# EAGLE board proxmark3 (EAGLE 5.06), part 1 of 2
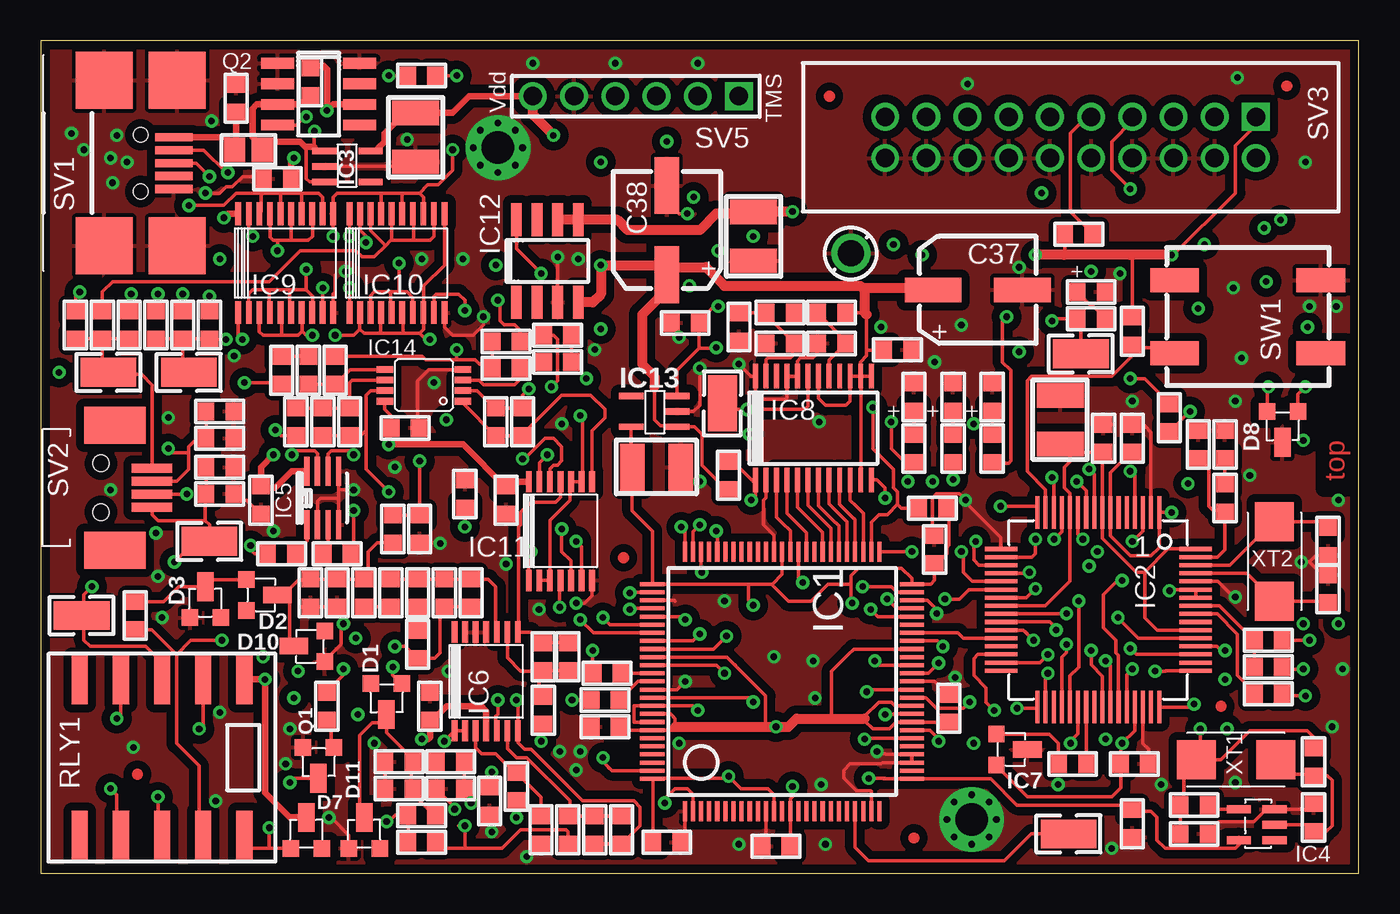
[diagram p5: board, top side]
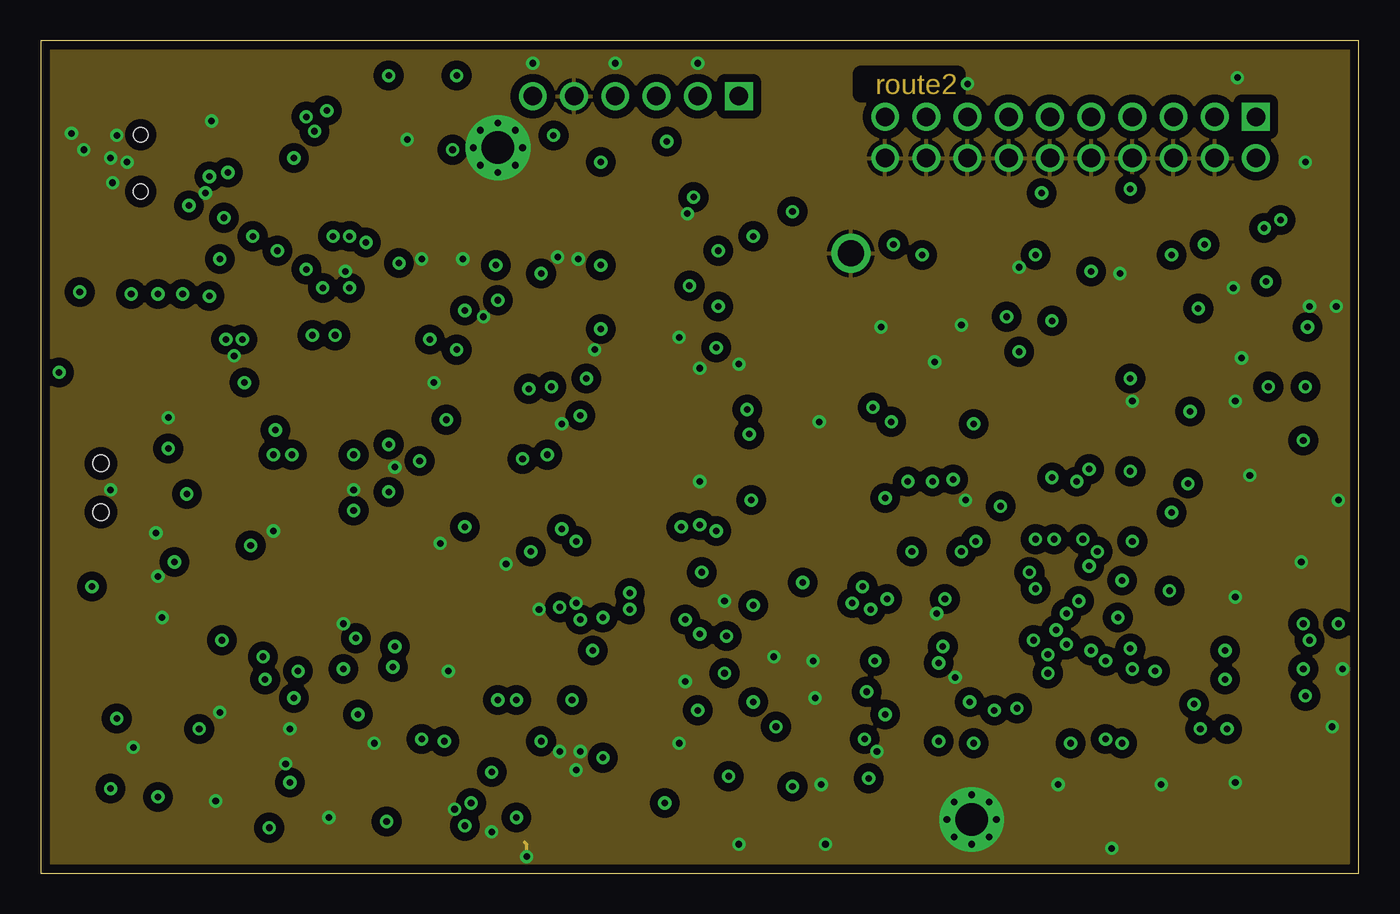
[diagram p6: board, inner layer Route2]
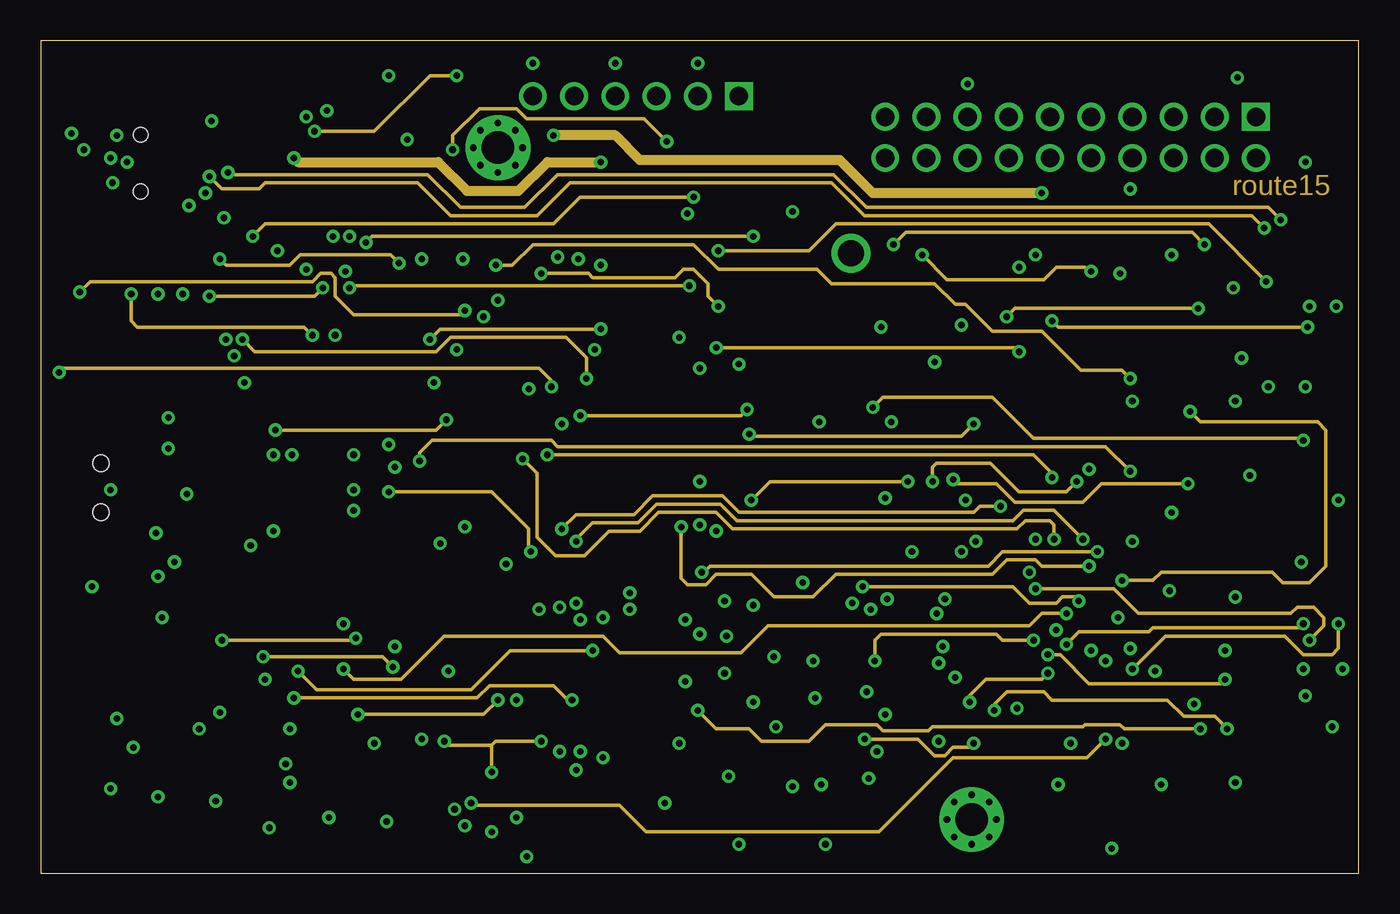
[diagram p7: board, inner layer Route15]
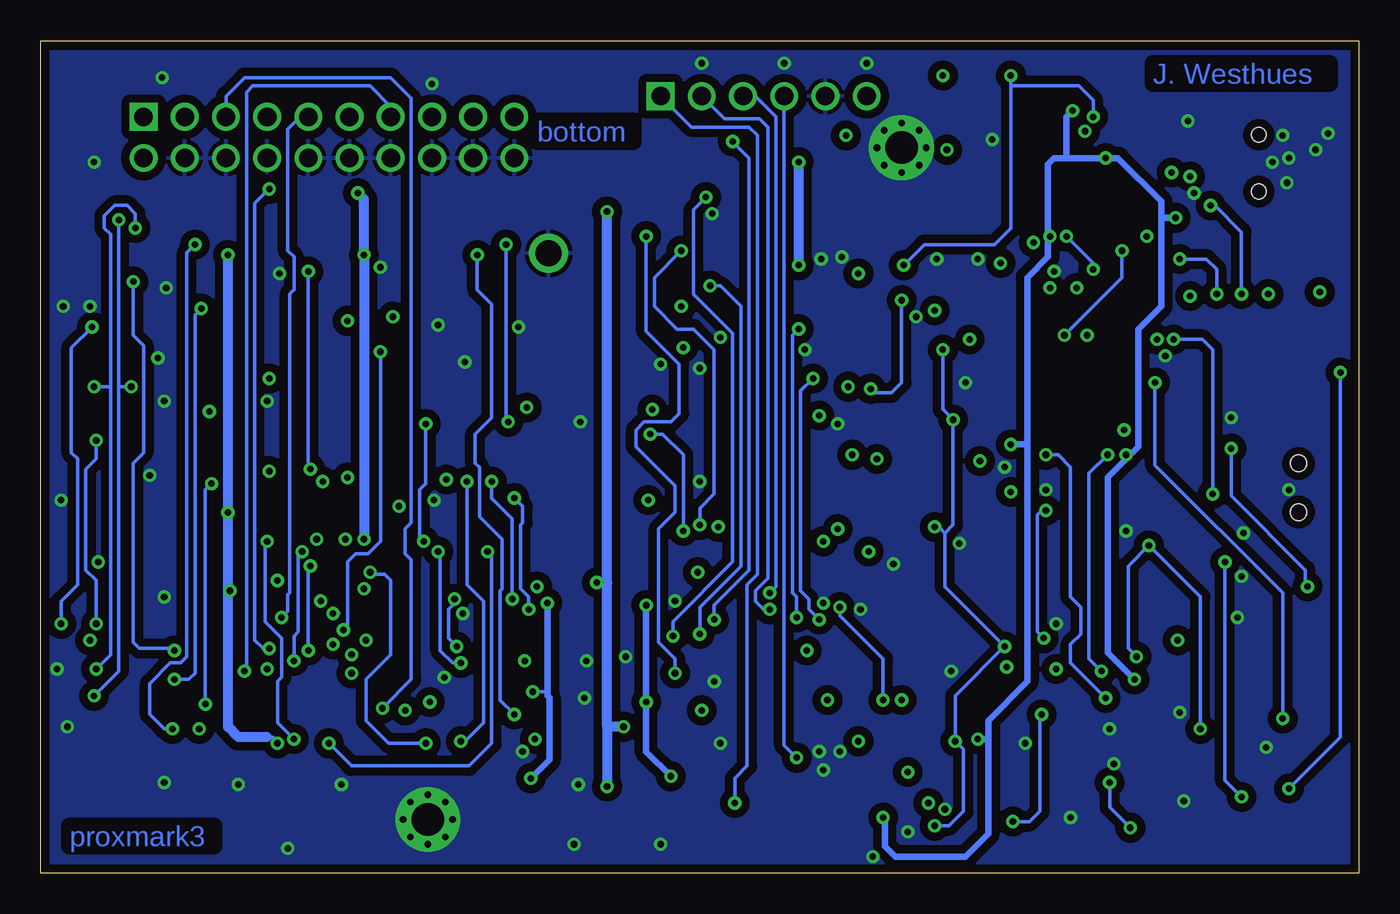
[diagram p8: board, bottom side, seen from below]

Size 81.28 x 51.31 mm. Coordinates in mm from the lower left corner, seen from the top.
Outline: 81.28,0 81.28,51.31 0,51.31 0,0 81.28,0
Copper layers (1*2*15*16): Top 0.0254mm / dielectric 0.508mm / Route2 0.0254mm / dielectric 0.508mm / Route15 0.0254mm / dielectric 0.508mm / Bottom 0.0254mm
Design rules "default *": minimum track width 8mil, minimum drill 16mil, track to track 8mil, track to pad 8mil, pad to pad 8mil, via to via 8mil, smd to smd 0mil, copper to edge 10mil, drill to drill 8mil, minimum pad ring 10mil, minimum via ring 8mil, stop-mask expansion 2mil, vias tented up to drill 16mil, thermal gap 10mil

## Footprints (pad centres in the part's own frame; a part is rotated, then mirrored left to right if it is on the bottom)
RLC_0603 = smd 1 x 1.1: 1 -0.85,0; 2 0.85,0
RLC_1210 = smd 1.5 x 2.9: 1 -1.5,0; 2 1.5,0
CAPCAITOR-ELECTROLYTIC-ALCHIP-MZA-F80 = smd 3.5 x 1.5: + 2.75,0; - -2.75,0
SOT23-3LEAD = smd 1.016 x 1.016: 1 -0.94,-0.762; 2 0.965,-0.762 | smd 1.016 x 1.778: 3 0.013,1.143
LED_0603 = smd 1 x 1.1: + -0.85,0; - 0.85,0
VQFP-100 = smd 1.25 x 0.25: 1 -8,6; 2 -8,5.5; 3 -8,5; 4 -8,4.5; 5 -8,4; 6 -8,3.5; 7 -8,3; 8 -8,2.5; 9 -8,2; 10 -8,1.5; 11 -8,1; 12 -8,0.5; 13 -8,0; 14 -8,-0.5; 15 -8,-1; 16 -8,-1.5; 17 -8,-2; 18 -8,-2.5; 19 -8,-3; 20 -8,-3.5; 21 -8,-4; 22 -8,-4.5; 23 -8,-5; 24 -8,-5.5; 25 -8,-6; 51 8,-6; 52 8,-5.5; 53 8,-5; 54 8,-4.5; 55 8,-4; 56 8,-3.5; 57 8,-3; 58 8,-2.5; 59 8,-2; 60 8,-1.5; 61 8,-1; 62 8,-0.5; 63 8,0; 64 8,0.5; 65 8,1; 66 8,1.5; 67 8,2; 68 8,2.5; 69 8,3; 70 8,3.5; 71 8,4; 72 8,4.5; 73 8,5; 74 8,5.5; 75 8,6 | smd 0.25 x 1.5: 26 -6,-8; 27 -5.5,-8; 28 -5,-8; 29 -4.5,-8; 30 -4,-8; 31 -3.5,-8; 32 -3,-8; 33 -2.5,-8; 34 -2,-8; 35 -1.5,-8; 36 -1,-8; 37 -0.5,-8; 38 0,-8; 39 0.5,-8; 40 1,-8; 41 1.5,-8; 42 2,-8; 43 2.5,-8; 44 3,-8; 45 3.5,-8; 46 4,-8; 47 4.5,-8; 48 5,-8; 49 5.5,-8; 50 6,-8; 76 6,8; 77 5.5,8; 78 5,8; 79 4.5,8; 80 4,8; 81 3.5,8; 82 3,8; 83 2.5,8; 84 2,8; 85 1.5,8; 86 1,8; 87 0.5,8; 88 0,8; 89 -0.5,8; 90 -1,8; 91 -1.5,8; 92 -2,8; 93 -2.5,8; 94 -3,8; 95 -3.5,8; 96 -4,8; 97 -4.5,8; 98 -5,8; 99 -5.5,8; 100 -6,8
LQFP-64 = smd 0.25 x 2: 1 0,0; 2 0.5,0; 3 1,0; 4 1.5,0; 5 2,0; 6 2.5,0; 7 3,0; 8 3.5,0; 9 4,0; 10 4.5,0; 11 5,0; 12 5.5,0; 13 6,0; 14 6.5,0; 15 7,0; 16 7.5,0; 33 7.5,12; 34 7,12; 35 6.5,12; 36 6,12; 37 5.5,12; 38 5,12; 39 4.5,12; 40 4,12; 41 3.5,12; 42 3,12; 43 2.5,12; 44 2,12; 45 1.5,12; 46 1,12; 47 0.5,12; 48 0,12 | smd 2 x 0.25: 17 9.75,2.25; 18 9.75,2.75; 19 9.75,3.25; 20 9.75,3.75; 21 9.75,4.25; 22 9.75,4.75; 23 9.75,5.25; 24 9.75,5.75; 25 9.75,6.25; 26 9.75,6.75; 27 9.75,7.25; 28 9.75,7.75; 29 9.75,8.25; 30 9.75,8.75; 31 9.75,9.25; 32 9.75,9.75; 49 -2.25,9.75; 50 -2.25,9.25; 51 -2.25,8.75; 52 -2.25,8.25; 53 -2.25,7.75; 54 -2.25,7.25; 55 -2.25,6.75; 56 -2.25,6.25; 57 -2.25,5.75; 58 -2.25,5.25; 59 -2.25,4.75; 60 -2.25,4.25; 61 -2.25,3.75; 62 -2.25,3.25; 63 -2.25,2.75; 64 -2.25,2.25
SOT-23-5 = smd 0.4 x 1.5: 1 -0.94,-1.422; 2 0.01,-1.422; 3 0.96,-1.422; 4 0.96,1.428; 5 -0.94,1.428
SMV-5 = smd 1.5 x 0.5: 1 0,0; 2 0,-0.95; 3 0,-1.9; 4 2.2,-1.9; 5 2.2,0
SOT-23-8-OR-MSOP-8 = smd 0.325 x 1.8: 1 -0.975,-1.65; 2 -0.325,-1.65; 3 0.325,-1.65; 4 0.975,-1.65; 5 0.975,1.65; 6 0.325,1.65; 7 -0.325,1.65; 8 -0.975,1.65
TSSOP-14 = smd 1.3 x 0.36: 1 0,0; 2 0,-0.65; 3 0,-1.3; 4 0,-1.95; 5 0,-2.6; 6 0,-3.25; 7 0,-3.9; 8 6.095,-3.9; 9 6.095,-3.25; 10 6.095,-2.6; 11 6.095,-1.95; 12 6.095,-1.3; 13 6.095,-0.65; 14 6.095,0
TSSOP-24 = smd 0.3 x 1.5: 1 -2.925,-3.2; 2 -2.275,-3.2; 3 -1.625,-3.2; 4 -0.975,-3.2; 5 -0.325,-3.2; 6 0.325,-3.2; 7 0.975,-3.2; 8 1.625,-3.2; 9 2.275,-3.2; 10 2.925,-3.2; 11 3.575,-3.2; 12 4.225,-3.2; 13 4.225,3.2; 14 3.575,3.2; 15 2.925,3.2; 16 2.275,3.2; 17 1.625,3.2; 18 0.975,3.2; 19 0.325,3.2; 20 -0.325,3.2; 21 -0.975,3.2; 22 -1.625,3.2; 23 -2.275,3.2; 24 -2.925,3.2
TSSOP-20 = smd 1.4 x 0.36: 1 0,0; 2 0,-0.65; 3 0,-1.3; 4 0,-1.95; 5 0,-2.6; 6 0,-3.25; 7 0,-3.9; 8 0,-4.55; 9 0,-5.2; 10 0,-5.85; 11 6.095,-5.85; 12 6.095,-5.2; 13 6.095,-4.55; 14 6.095,-3.9; 15 6.095,-3.25; 16 6.095,-2.6; 17 6.095,-1.95; 18 6.095,-1.3; 19 6.095,-0.65; 20 6.095,0
SOIC-8 = smd 0.66 x 2.032: 1 0,0; 2 1.27,0; 3 2.54,0; 4 3.81,0; 5 3.81,5.08; 6 2.54,5.08; 7 1.27,5.08; 8 0,5.08
MSOP8 = smd 0.41 x 1.02: 1 0,0; 2 0.65,0; 3 1.3,0; 4 1.95,0; 5 1.95,4.8; 6 1.3,4.8; 7 0.65,4.8; 8 0,4.8
TQ-SMD-RELAY = smd 1 x 3: 1 -5.08,-4.78; 2 -2.54,-4.78; 3 0,-4.78; 4 2.54,-4.78; 5 5.08,-4.78; 6 5.08,4.78; 7 2.54,4.78; 8 0,4.78; 9 -2.54,4.78; 10 -5.08,4.78
USB-MINIB-SMD = smd 2.3 x 0.5: 1 2,0.4; 2 2,-0.4; 3 2,-1.2; 4 2,-2; 5 2,-2.8 | smd 3.5 x 3.5: TAB0 -2.3,3.9; TAB1 2.2,3.9; TAB2 2.2,-6.3; TAB3 -2.3,-6.3 | hole 0.9: -0.05,0.55; -0.05,-2.95
HIROSE-MQ172-4POS = smd 0.55 x 2.5: 1 -1.2,6.75; 2 -0.4,6.75; 3 0.4,6.75; 4 1.2,6.75 | smd 2.3 x 3.8: P$1 -3.85,4.45; P$2 3.85,4.45 | hole 1: -1.5,3.6; 1.5,3.6
HEADER-MALE-10X2-0.100-SHROUDED = drill 1.143 square: 1 -1.27,11.43 | drill 1.143 round: 2 1.27,11.43; 3 -1.27,8.89; 4 1.27,8.89; 5 -1.27,6.35; 6 1.27,6.35; 7 -1.27,3.81; 8 1.27,3.81; 9 -1.27,1.27; 10 1.27,1.27; 11 -1.27,-1.27; 12 1.27,-1.27; 13 -1.27,-3.81; 14 1.27,-3.81; 15 -1.27,-6.35; 16 1.27,-6.35; 17 -1.27,-8.89; 18 1.27,-8.89; 19 -1.27,-11.43; 20 1.27,-11.43
HEADER-MALE-6X1-0.100-UNKEYED = drill 1.143 square: 1 0,6.35 | drill 1.143 round: 2 0,3.81; 3 0,1.27; 4 0,-1.27; 5 0,-3.81; 6 0,-6.35
TACTSWITCH-SMD-EVQQ1 = smd 1.5 x 3: A -2.25,4.5; B 2.25,-4.5; P$2 2.25,4.5; P$3 -2.25,-4.5
KEYSTONE-SMD-TESTPOINT-5015 = smd 3.429 x 1.778: 1 0,0
KEYSTONE-PTH-TESTPOINT-5011 = drill 1.6 round: A 0,0
RLC_0805 = smd 1.3 x 1.5: 1 -0.85,0; 2 0.85,0
XTAL-SMD-CITIZEN-CS10 = smd 2.4 x 2.4: A -0.2,0; B 4.7,0

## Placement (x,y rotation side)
C1  33n  [RLC_0603]  12.06,47.75 90 top
C2  22p  [RLC_0603]  78.49,3.43 90 top
C3  22p  [RLC_0603]  71.12,2.41 0 top
C4  33n  [RLC_0603]  73.03,26.42 270 top
C5  2n  [RLC_0603]  71.37,26.42 270 top
C6  22p  [RLC_0603]  79.38,17.53 270 top
C7  22p  [RLC_0603]  79.38,20.45 90 top
C8  1n  [RLC_0603]  65.53,26.8 90 top
C9  2u2  [RLC_1210]  62.87,27.94 90 top
C10  100n  [RLC_0603]  27.69,4.45 270 top
C11  1n  [RLC_0603]  22.1,6.86 180 top
C12  1n  [RLC_0603]  23.5,3.56 180 top
C13  dnp  [RLC_0603]  35.81,2.67 270 top
C14  22p  [RLC_0603]  5.84,15.88 90 top
C15  130p  [RLC_0603]  16.64,17.27 270 top
C16  1n  [RLC_0603]  21.59,17.27 90 top
C17  dnp  [RLC_0603]  32.51,13.34 90 top
C18  33n  [RLC_0603]  45.59,32.64 180 top
C19  33n  [RLC_0603]  48.77,32.64 180 top
C20  dnp  [RLC_0603]  11.05,28.45 0 top
C21  33n  [RLC_0603]  24,10.29 90 top
C22  33n  [RLC_0603]  22.48,27.43 0 top
C23  33n  [RLC_0603]  13.59,22.99 270 top
C24  33n  [RLC_0603]  28.7,22.99 270 top
C25  33n  [RLC_0603]  67.44,6.73 0 top
C26  33n  [RLC_0603]  67.31,26.8 90 top
C27  4u7  [RLC_1210]  23.11,45.34 270 top
C28  33n  [RLC_0603]  38.61,1.91 0 top
C29  33n  [RLC_0603]  34.8,9.02 180 top
C30  33n  [RLC_0603]  45.34,1.65 180 top
C31  33n  [RLC_0603]  56.01,10.16 90 top
C32  33n  [RLC_0603]  55.12,19.94 90 top
C33  4u7  [RLC_1210]  43.94,39.24 270 top
C34  4u7  [RLC_1210]  37.97,25.02 0 top
C35  47p  [RLC_0603]  11.05,25.02 0 top
C36  dnp  [RLC_0603]  11.05,23.37 0 top
C37  100u  [CAPCAITOR-ELECTROLYTIC-ALCHIP-MZA-F80]  57.78,35.94 180 top
C38  100u  [CAPCAITOR-ELECTROLYTIC-ALCHIP-MZA-F80]  38.61,39.62 270 top
C39  1n  [RLC_0603]  11.05,26.8 0 top
C40  dnp  [RLC_0603]  29.72,27.81 270 top
C41  dnp  [RLC_0603]  19.05,27.81 270 top
C42  1n  [RLC_0603]  31.88,33.15 0 top
C43  1n  [RLC_0603]  14.86,30.99 90 top
C44  33n  [RLC_0603]  52.83,32.26 0 top
C45  100n  [RLC_0603]  26.16,23.37 90 top
C46  33n  [RLC_0603]  14.61,42.8 180 top
C47  33n  [RLC_0603]  67.31,3.05 270 top
D1  DIODE-SMD-SOT23  [SOT23-3LEAD]  21.34,10.92 180 top
D2  DIODE-SMD-SOT23  [SOT23-3LEAD]  13.46,17.14 270 top
D3  DIODE-SMD-SOT23  [SOT23-3LEAD]  10.16,16.51 0 top
D4  LED  [LED_0603]  56.26,29.34 90 top
D5  LED  [LED_0603]  58.67,29.34 90 top
D6  LED  [LED_0603]  53.85,29.34 90 top
D7  DIODE-SMD-SOT23  [SOT23-3LEAD]  16.38,2.29 0 top
D8  DUAL-TVS-COMMON-ANODE  [SOT23-3LEAD]  76.58,27.69 180 top
D9  LED  [LED_0603]  64.77,35.81 0 top
D10  DIODE-SMD-SOT23  [SOT23-3LEAD]  16.76,13.97 90 top
D11  DIODE-SMD-SOT23  [SOT23-3LEAD]  19.94,2.29 0 top
IC1  SPARTAN-II-XC2S30-100-VQFP  [VQFP-100]  45.72,11.81 90 top
IC2  AT91SAM7S64  [LQFP-64]  68.96,22.23 180 top
IC3  PQ1X331M2ZP-3V3-LDO-SOT-23-5  [SOT-23-5]  18.92,43.56 270 top
IC4  HCU-INVERTER  [SMV-5]  76.07,2.03 180 top
IC5  TLV3502  [SOT-23-8-OR-MSOP-8]  17.4,23.11 0 top
IC6  MCP6294  [TSSOP-14]  25.53,8.76 90 top
IC7  MCP100  [SOT23-3LEAD]  59.69,7.62 270 top
IC8  TLC5540  [TSSOP-24]  46.99,27.43 0 top
IC9  74XX244-OCTAL-TRISTATE-BUFFERS  [TSSOP-20]  12.19,34.54 90 top
IC10  74XX244-OCTAL-TRISTATE-BUFFERS  [TSSOP-20]  19.05,34.54 90 top
IC11  CD4066  [TSSOP-14]  30.1,18.03 90 top
IC12  LP2989AIM-2.5  [SOIC-8]  29.34,35.18 0 top
IC13  PQ1X331M2ZP-3V3-LDO-SOT-23-5  [SOT-23-5]  37.85,28.45 90 top
IC14  AD8052  [MSOP8]  26.04,29.08 90 top
Q1  NPN-SOT23-2N3904  [SOT23-3LEAD]  17.14,6.99 180 top
Q2  IRF7307  [SOIC-8]  14.61,49.91 270 top
R1  1meg  [RLC_0603]  78.49,6.86 90 top
R2  100  [RLC_0603]  71.12,4.19 180 top
R3  330  [RLC_0603]  73.03,23.11 270 top
R4  27  [RLC_0603]  75.69,11.05 180 top
R5  27  [RLC_0603]  75.69,12.7 180 top
R6  1k5  [RLC_0603]  75.69,14.35 0 top
R7  10k  [RLC_0603]  64.01,39.37 180 top
R8  10k  [RLC_0603]  63.63,6.73 0 top
R9  100k  [RLC_0603]  29.34,5.33 270 top
R10  100k  [RLC_0603]  30.86,2.67 90 top
R11  510k  [RLC_0603]  22.1,5.21 0 top
R12  100k  [RLC_0603]  23.5,1.91 180 top
R13  10k  [RLC_0603]  32.51,2.67 90 top
R14  10k  [RLC_0603]  34.16,2.67 270 top
R15  10k  [RLC_0603]  18.29,17.27 90 top
R16  zerohm  [RLC_0603]  19.94,17.27 270 top
R17  10k  [RLC_0603]  24.89,17.27 90 top
R18  10k  [RLC_0603]  30.99,13.34 90 top
R19  10k  [RLC_0603]  30.99,10.03 90 top
R20  240k  [RLC_0603]  14.86,19.68 0 top
R21  24k  [RLC_0603]  18.29,19.68 180 top
R22  33  [RLC_0603]  5.46,33.78 270 top
R23  1k  [RLC_0603]  39.75,33.91 0 top
R24  330  [RLC_0603]  56.26,26.16 90 top
R25  330  [RLC_0603]  58.67,26.16 90 top
R26  330  [RLC_0603]  53.85,26.16 90 top
R27  33  [RLC_0603]  7.11,33.78 270 top
R28  33  [RLC_0603]  3.81,33.78 270 top
R29  33  [RLC_0603]  8.76,33.78 270 top
R30  10meg  [RLC_0603]  25.27,6.86 0 top
R31  240k  [RLC_0603]  25.27,5.21 0 top
R32  zerohm  [RLC_0603]  16.51,30.99 270 top
R33  2k4  [RLC_0603]  28.07,27.81 270 top
R34  10k  [RLC_0603]  17.4,27.81 270 top
R35  zerohm  [RLC_0603]  31.88,31.5 180 top
R36  dnp  [RLC_0603]  26.54,17.27 90 top
R37  dnp  [RLC_0603]  23.24,17.27 270 top
R38  dnp  [RLC_0603]  23.24,14.1 90 top
R39  1k  [RLC_0603]  34.92,12.32 0 top
R40  10k  [RLC_0603]  17.65,10.29 270 top
R41  10meg  [RLC_0603]  21.72,21.21 90 top
R42  1meg  [RLC_0603]  23.37,21.21 90 top
R43  1k  [RLC_0603]  67.31,33.4 90 top
R44  1k  [RLC_0603]  34.8,10.67 0 top
R45  10k  [RLC_0603]  10.41,33.78 270 top
R46  10k  [RLC_0603]  2.16,33.78 270 top
R47  10k  [RLC_0603]  42.42,24.51 90 top
R48  dnp  [RLC_0603]  18.16,30.99 270 top
R49  2k4  [RLC_0603]  28.7,31.11 0 top
R50  10k  [RLC_0603]  15.75,27.81 90 top
R51  2k4  [RLC_0603]  28.7,32.77 0 top
R52  100  [RLC_0603]  48.77,34.54 0 top
R53  330  [RLC_0603]  45.59,34.54 0 top
R54  100  [RLC_0603]  43.05,33.66 90 top
R55  330  [RLC_0603]  64.77,34.16 0 top
R56  10k  [RLC_0603]  23.5,49.15 0 top
R57  10k  [RLC_0603]  69.6,28.07 90 top
R58  dnp  [RLC_0603]  16.64,48.77 270 top
R59  3k3  [RLC_0603]  54.99,22.48 0 top
RLY1  RELAY-DPDT  [TQ-SMD-RELAY]  7.49,7.11 180 top
SV1  USB-MINIB  [USB-MINIB-SMD]  6.22,44.96 0 top
SV2  HIROSE-MQ172-4POS  [HIROSE-MQ172-4POS]  0.13,23.75 270 top
SV3  JTAG  [HEADER-MALE-10X2-0.100-SHROUDED]  63.5,45.34 270 top
SV5  HEADER-MALE-6X1  [HEADER-MALE-6X1-0.100-UNKEYED]  36.7,47.88 270 top
SW1  TACTSWITCH  [TACTSWITCH-SMD-EVQQ1]  74.42,34.29 270 top
TP1  TESTPADKEYSTONE-SMD  [KEYSTONE-SMD-TESTPOINT-5015]  42.04,28.96 90 top
TP2  TESTPADKEYSTONE-SMD  [KEYSTONE-SMD-TESTPOINT-5015]  2.54,15.88 180 top
TP3  TESTPADKEYSTONE-SMD  [KEYSTONE-SMD-TESTPOINT-5015]  10.41,20.45 180 top
TP4  TESTPADKEYSTONE-SMD  [KEYSTONE-SMD-TESTPOINT-5015]  9.14,30.86 180 top
TP5  TESTPADKEYSTONE-SMD  [KEYSTONE-SMD-TESTPOINT-5015]  4.19,30.86 180 top
TP6  TESTPADKEYSTONE-PTH  [KEYSTONE-PTH-TESTPOINT-5011]  49.95,38.19 45 top
TP7  TESTPADKEYSTONE-SMD  [KEYSTONE-SMD-TESTPOINT-5015]  63.37,2.41 180 top
TP8  TESTPADKEYSTONE-SMD  [KEYSTONE-SMD-TESTPOINT-5015]  64.14,32 180 top
U1  FERRITE0805  [RLC_0805]  12.83,44.58 0 top
XT1  XTAL-SMD-CITIZEN-CS10  [XTAL-SMD-CITIZEN-CS10]  75.95,6.99 180 top
XT2  XTAL-SMD-CITIZEN-CS10  [XTAL-SMD-CITIZEN-CS10]  76.07,21.46 270 top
